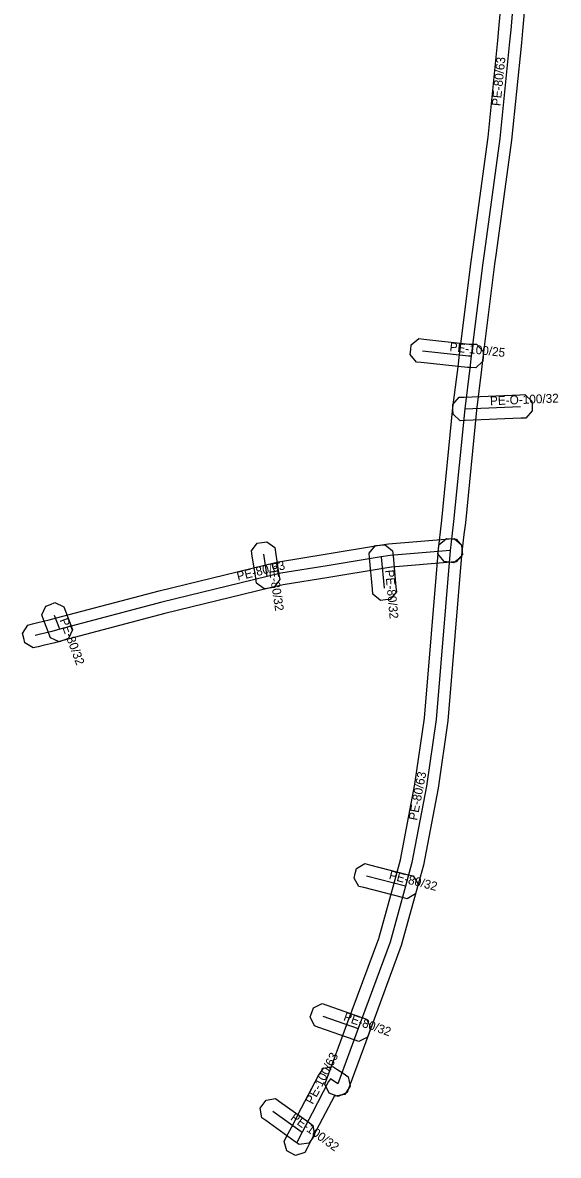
# Model space of a CAD drawing. Extents: x -569373 to -565022, y -1135090 to -1131496.
# Drawn here: x -565774 to -565728.4, y -1133980.1 to -1133883.9 of the extents above; entities that cross this region are included whole.
import ezdxf

# ---------------------------------------------------------------- set-up
doc = ezdxf.new("R2010")
doc.units = 0
for name, color, linetype in [('1', 7, 'Continuous'), ('24', 7, 'Continuous'), ('30', 7, 'Continuous')]:
    doc.layers.add(name, color=color, linetype=linetype)

msp = doc.modelspace()

# ---------------------------------------------------------------- linework, layer by layer
at = {"layer": '1'}
msp.add_lwpolyline([(-565731.094, -1133880.199), (-565731.484, -1133884.559), (-565731.575, -1133885.566), (-565732.417, -1133893.829), (-565733.728, -1133903.4), (-565733.851, -1133904.384), (-565734.838, -1133912.294), (-565734.968, -1133913.34), (-565735.399, -1133916.778), (-565736.336, -1133926.357), (-565736.454, -1133927.357), (-565736.627, -1133928.827), (-565736.675, -1133929.238), (-565737.326, -1133929.751), (-565737.737, -1133929.703), (-565738.148, -1133929.655), (-565738.661, -1133929.004), (-565738.613, -1133928.593), (-565738.44, -1133927.123), (-565738.324, -1133926.143), (-565737.387, -1133916.556), (-565736.952, -1133913.092), (-565736.822, -1133912.046), (-565735.835, -1133904.136), (-565735.712, -1133903.14), (-565734.403, -1133893.591), (-565733.565, -1133885.374), (-565733.476, -1133884.381), (-565733.086, -1133880.021)], dxfattribs=at)
for points in [[(-565740.285, -1133910.702), (-565739.873, -1133910.746), (-565736.006, -1133911.162), (-565735.79, -1133911.171), (-565735.376, -1133911.188), (-565734.814, -1133911.796), (-565734.831, -1133912.21), (-565734.848, -1133912.624), (-565735.456, -1133913.186), (-565735.87, -1133913.169), (-565736.154, -1133913.158), (-565740.087, -1133912.734), (-565740.499, -1133912.69), (-565741.018, -1133912.045), (-565740.974, -1133911.633), (-565740.93, -1133911.221)], [(-565736.849, -1133915.685), (-565736.435, -1133915.668), (-565731.702, -1133915.471), (-565731.288, -1133915.454), (-565730.678, -1133916.014), (-565730.661, -1133916.428), (-565730.644, -1133916.842), (-565731.204, -1133917.452), (-565731.618, -1133917.469), (-565736.351, -1133917.666), (-565736.765, -1133917.683), (-565737.375, -1133917.123), (-565737.392, -1133916.709), (-565737.409, -1133916.295)], [(-565737.125, -1133929.673), (-565737.538, -1133929.707), (-565742.619, -1133930.123), (-565743.318, -1133930.237), (-565747.93, -1133931.007), (-565751.814, -1133931.621), (-565752.934, -1133931.892), (-565761.884, -1133934.069), (-565770.561, -1133936.366), (-565771.233, -1133936.549), (-565772.216, -1133936.782), (-565772.663, -1133936.891), (-565773.065, -1133936.99), (-565773.773, -1133936.56), (-565773.871, -1133936.157), (-565773.97, -1133935.755), (-565773.54, -1133935.047), (-565773.137, -1133934.949), (-565772.684, -1133934.838), (-565771.727, -1133934.611), (-565771.079, -1133934.434), (-565762.376, -1133932.131), (-565753.406, -1133929.948), (-565752.206, -1133929.659), (-565748.25, -1133929.033), (-565743.642, -1133928.263), (-565742.861, -1133928.137), (-565737.702, -1133927.713), (-565737.289, -1133927.679), (-565736.657, -1133928.215), (-565736.623, -1133928.628), (-565736.589, -1133929.041)], [(-565736.589, -1133928.38), (-565736.623, -1133928.793), (-565737.816, -1133943.173), (-565738.644, -1133948.906), (-565739.905, -1133955.447), (-565740.466, -1133957.495), (-565741.787, -1133962.287), (-565744.522, -1133969.686), (-565746.25, -1133974.37), (-565746.393, -1133974.759), (-565747.145, -1133975.105), (-565747.534, -1133974.962), (-565747.923, -1133974.819), (-565748.269, -1133974.067), (-565748.126, -1133973.678), (-565746.398, -1133968.994), (-565743.693, -1133961.673), (-565742.394, -1133956.965), (-565741.855, -1133954.993), (-565740.616, -1133948.574), (-565739.804, -1133942.947), (-565738.617, -1133928.627), (-565738.583, -1133928.214), (-565737.95, -1133927.679), (-565737.537, -1133927.713), (-565737.124, -1133927.747)], [(-565754.097, -1133931.48), (-565754.159, -1133931.07), (-565754.449, -1133929.16), (-565754.511, -1133928.75), (-565754.02, -1133928.083), (-565753.61, -1133928.021), (-565753.2, -1133927.959), (-565752.533, -1133928.45), (-565752.471, -1133928.86), (-565752.181, -1133930.77), (-565752.119, -1133931.18), (-565752.61, -1133931.847), (-565753.02, -1133931.909), (-565753.43, -1133931.971)], [(-565742.523, -1133928.744), (-565742.484, -1133929.156), (-565742.234, -1133931.816), (-565742.195, -1133932.229), (-565742.724, -1133932.867), (-565743.136, -1133932.906), (-565743.549, -1133932.945), (-565744.187, -1133932.416), (-565744.226, -1133932.004), (-565744.476, -1133929.344), (-565744.515, -1133928.931), (-565743.986, -1133928.293), (-565743.574, -1133928.254), (-565743.161, -1133928.215)], [(-565771.612, -1133936.137), (-565771.757, -1133935.749), (-565772.197, -1133934.569), (-565772.342, -1133934.181), (-565771.997, -1133933.428), (-565771.609, -1133933.283), (-565771.221, -1133933.138), (-565770.468, -1133933.483), (-565770.323, -1133933.871), (-565769.883, -1133935.051), (-565769.738, -1133935.439), (-565770.083, -1133936.192), (-565770.471, -1133936.337), (-565770.859, -1133936.482)], [(-565741.276, -1133958.301), (-565741.677, -1133958.199), (-565744.977, -1133957.359), (-565745.378, -1133957.257), (-565745.801, -1133956.544), (-565745.699, -1133956.143), (-565745.597, -1133955.742), (-565744.884, -1133955.319), (-565744.483, -1133955.421), (-565741.183, -1133956.261), (-565740.782, -1133956.363), (-565740.359, -1133957.076), (-565740.461, -1133957.477), (-565740.563, -1133957.878)], [(-565748.51, -1133967.209), (-565748.119, -1133967.346), (-565745.129, -1133968.396), (-565744.738, -1133968.534), (-565744.379, -1133969.28), (-565744.516, -1133969.671), (-565744.654, -1133970.062), (-565745.4, -1133970.421), (-565745.791, -1133970.284), (-565748.781, -1133969.234), (-565749.172, -1133969.096), (-565749.531, -1133968.35), (-565749.394, -1133967.959), (-565749.256, -1133967.568)], [(-565747.397, -1133975.086), (-565747.468, -1133975.039), (-565748.483, -1133976.982), (-565749.322, -1133978.6), (-565749.782, -1133979.488), (-565749.973, -1133979.856), (-565750.762, -1133980.107), (-565751.13, -1133979.916), (-565751.498, -1133979.725), (-565751.749, -1133978.936), (-565751.558, -1133978.568), (-565751.098, -1133977.68), (-565750.257, -1133976.058), (-565748.827, -1133973.321), (-565748.631, -1133973.039), (-565748.398, -1133972.704), (-565747.596, -1133972.552), (-565747.256, -1133972.778), (-565746.634, -1133973.192), (-565746.289, -1133973.421), (-565746.126, -1133974.233), (-565746.356, -1133974.578), (-565746.585, -1133974.923)], [(-565752.462, -1133975.286), (-565752.126, -1133975.528), (-565749.626, -1133977.328), (-565749.29, -1133977.57), (-565749.156, -1133978.388), (-565749.398, -1133978.724), (-565749.64, -1133979.06), (-565750.458, -1133979.194), (-565750.794, -1133978.952), (-565753.294, -1133977.152), (-565753.63, -1133976.91), (-565753.764, -1133976.092), (-565753.522, -1133975.756), (-565753.28, -1133975.42)]]:
    msp.add_lwpolyline(points, close=True, dxfattribs=at)
at = {"layer": '24'}
for points in [[(-565729.19, -1133853.47), (-565730.14, -1133862.17), (-565731.67, -1133875.37), (-565732.09, -1133880.11), (-565732.48, -1133884.47), (-565732.57, -1133885.47), (-565733.41, -1133893.71), (-565734.72, -1133903.27), (-565734.843, -1133904.26), (-565735.83, -1133912.17), (-565735.96, -1133913.216), (-565736.393, -1133916.667), (-565737.33, -1133926.25), (-565737.447, -1133927.24), (-565737.62, -1133928.71)], [(-565739.98, -1133911.74), (-565736.08, -1133912.16), (-565735.83, -1133912.17)], [(-565736.393, -1133916.667), (-565731.66, -1133916.47)], [(-565737.62, -1133928.71), (-565742.74, -1133929.13), (-565743.48, -1133929.25), (-565748.09, -1133930.02), (-565752.01, -1133930.64), (-565753.17, -1133930.92), (-565762.13, -1133933.1), (-565770.82, -1133935.4), (-565771.48, -1133935.58), (-565772.45, -1133935.81), (-565772.9, -1133935.92)], [(-565737.62, -1133928.71), (-565738.81, -1133943.06), (-565739.63, -1133948.74), (-565740.88, -1133955.22), (-565741.43, -1133957.23), (-565742.74, -1133961.98), (-565745.46, -1133969.34), (-565747.188, -1133974.024)], [(-565753.17, -1133930.92), (-565753.46, -1133929.01)], [(-565743.48, -1133929.25), (-565743.23, -1133931.91)], [(-565770.82, -1133935.4), (-565771.26, -1133934.22)], [(-565741.43, -1133957.23), (-565744.73, -1133956.39)], [(-565748.45, -1133968.29), (-565745.46, -1133969.34)], [(-565747.188, -1133974.024), (-565747.81, -1133973.61), (-565747.97, -1133973.84), (-565749.37, -1133976.52), (-565750.21, -1133978.14), (-565750.67, -1133979.028)], [(-565752.71, -1133976.34), (-565750.21, -1133978.14)]]:
    msp.add_lwpolyline(points, dxfattribs=at)

# ---------------------------------------------------------------- texts
at = {"layer": '30'}
for s, rotation, p in [('PE-80/63', 84.17928, (-565733.351, -1133890.97)), ('PE-100/25', 353.85337, (-565737.706, -1133911.763)), ('PE-O-100/32', 2.38343, (-565734.226, -1133916.369)), ('PE-80/63', 13.67457, (-565755.669, -1133931.279)), ('PE-80/32', 278.63342, (-565753.115, -1133929.765)), ('PE-80/32', 275.36917, (-565743.155, -1133930.38)), ('PE-80/32', 290.44955, (-565770.84, -1133934.61)), ('PE-80/63', 79.08168, (-565740.437, -1133951.688)), ('PE-80/32', 345.7189, (-565742.88, -1133956.61)), ('PE-80/32', 340.65023, (-565746.755, -1133968.615)), ('PE-100/63', 62.41797, (-565749.309, -1133975.821)), ('PE-100/32', 324.24611, (-565751.26, -1133977.04))]:
    msp.add_text(s, height=0.75, rotation=rotation, dxfattribs=at).set_placement(p)

doc.saveas('drawing.dxf')
